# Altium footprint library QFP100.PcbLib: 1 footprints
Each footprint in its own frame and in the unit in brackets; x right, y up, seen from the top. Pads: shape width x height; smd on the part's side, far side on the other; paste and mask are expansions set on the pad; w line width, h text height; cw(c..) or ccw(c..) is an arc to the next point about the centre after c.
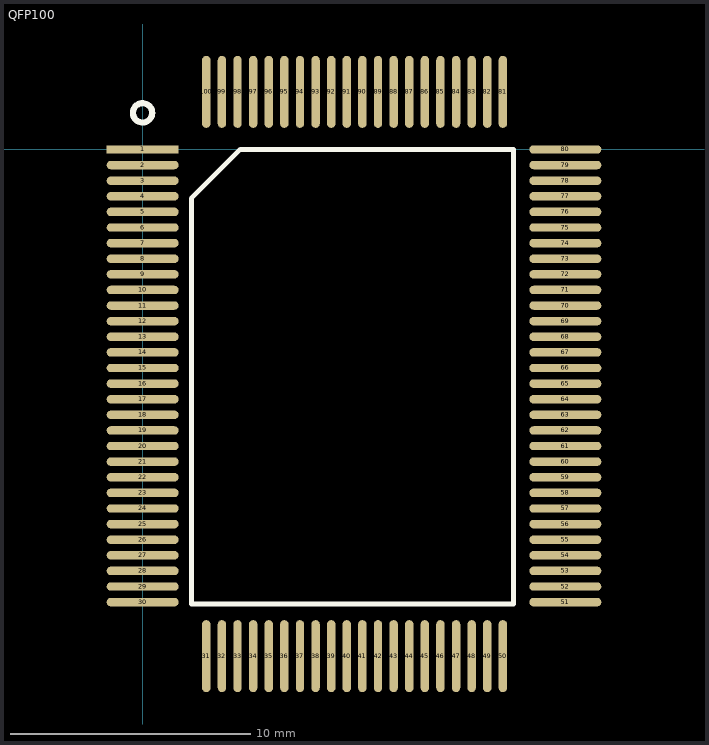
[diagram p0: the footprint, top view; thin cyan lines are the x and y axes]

## QFP100 [mm]
pads (100):
  rect 3x0.35 smd: 1(0.004,-0.001)
  oval 3x0.35 smd: 2(0.004,-0.651) 3(0.004,-1.301) 4(0.004,-1.951) 5(0.004,-2.601) 6(0.004,-3.251) 7(0.004,-3.901) 8(0.004,-4.551) 9(0.004,-5.201) 10(0.004,-5.851) 11(0.004,-6.501) 12(0.004,-7.151) 13(0.004,-7.801) 14(0.004,-8.451) 15(0.004,-9.101) 16(0.004,-9.751) 17(0.004,-10.401) 18(0.004,-11.051) 19(0.004,-11.701) 20(0.004,-12.351) 21(0.004,-13.001) 22(0.004,-13.651) 23(0.004,-14.301) 24(0.004,-14.951) 25(0.004,-15.601) 26(0.004,-16.251) 27(0.004,-16.901) 28(0.004,-17.551) 29(0.004,-18.201) 30(0.004,-18.851) 51(17.604,-18.851) 52(17.604,-18.201) 53(17.604,-17.551) 54(17.604,-16.901) 55(17.604,-16.251) 56(17.604,-15.601) 57(17.604,-14.951) 58(17.604,-14.301) 59(17.604,-13.651) 60(17.604,-13.001) 61(17.604,-12.351) 62(17.604,-11.701) 63(17.604,-11.051) 64(17.604,-10.401) 65(17.604,-9.751) 66(17.604,-9.101) 67(17.604,-8.451) 68(17.604,-7.801) 69(17.604,-7.151) 70(17.604,-6.501) 71(17.604,-5.851) 72(17.604,-5.201) 73(17.604,-4.551) 74(17.604,-3.901) 75(17.604,-3.251) 76(17.604,-2.601) 77(17.604,-1.951) 78(17.604,-1.301) 79(17.604,-0.651) 80(17.604,-0.001)
  oval 0.35x3 smd: 31(2.654,-21.101) 32(3.304,-21.101) 33(3.954,-21.101) 34(4.604,-21.101) 35(5.254,-21.101) 36(5.904,-21.101) 37(6.554,-21.101) 38(7.204,-21.101) 39(7.854,-21.101) 40(8.504,-21.101) 41(9.154,-21.101) 42(9.804,-21.101) 43(10.454,-21.101) 44(11.104,-21.101) 45(11.754,-21.101) 46(12.404,-21.101) 47(13.054,-21.101) 48(13.704,-21.101) 49(14.354,-21.101) 50(15.004,-21.101) 81(15.004,2.399) 82(14.354,2.399) 83(13.704,2.399) 84(13.054,2.399) 85(12.404,2.399) 86(11.754,2.399) 87(11.104,2.399) 88(10.454,2.399) 89(9.804,2.399) 90(9.154,2.399) 91(8.504,2.399) 92(7.854,2.399) 93(7.204,2.399) 94(6.554,2.399) 95(5.904,2.399) 96(5.254,2.399) 97(4.604,2.399) 98(3.954,2.399) 99(3.304,2.399) 100(2.654,2.399)
Top Overlay:
  circle w0.254: c0,1.524 r0.403
  lines w0.2: 2.032,-18.924 2.032,-2.032 4.064,0 15.444,0 15.444,-18.924 2.032,-18.924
